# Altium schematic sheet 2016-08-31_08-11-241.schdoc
size 331 x 127 mm; SheetNumber: 1; SheetTotal: 1
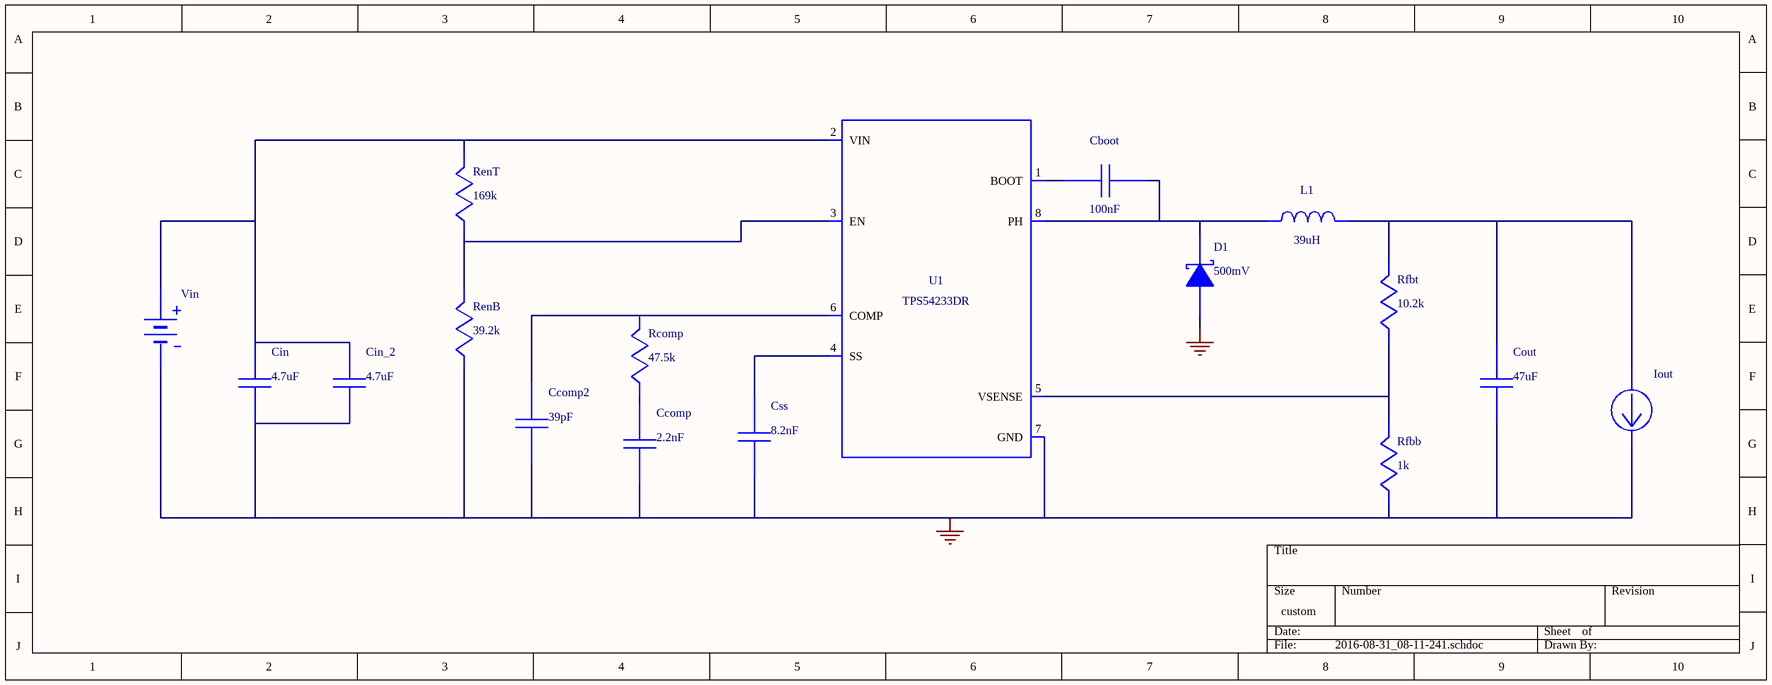
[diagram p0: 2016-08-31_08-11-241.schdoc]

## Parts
Cboot  value 100nF  (hidden comment: GRM155R61A104KA01D)
Ccomp  value 2.2nF  (hidden comment: CC0805KRX7R9BB222)
Ccomp2  value 39pF  (hidden comment: CC0805JRNPO9BN390)
Cin  value 4.7uF  (hidden comment: GRM32ER71H475KA88L)
Cin_2  value 4.7uF  (hidden comment: GRM32ER71H475KA88L)
Cout  value 47uF  (hidden comment: GRM32ER61C476ME15L)
Css  value 8.2nF  (hidden comment: GRM033R61A822KA01D)
D1  value 500mV  (hidden comment: B240A-13-F)
Iout  WB_CURRENT_LOAD  (value not drawn)
L1  value 39uH  (hidden comment: SRR1208-390YL)
Rcomp  value 47.5k  (hidden comment: CRCW040247K5FKED)
RenB  value 39.2k  (hidden comment: CRCW040239K2FKED)
RenT  value 169k  (hidden comment: CRCW0402169KFKED)
Rfbb  value 1k  (hidden comment: CRCW04021K00FKED)
Rfbt  value 10.2k  (hidden comment: CRCW040210K2FKED)
U1  TPS54231DR  (value not drawn)
Vin  WB_BATTERY  (value not drawn)

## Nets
0: Ccomp.2 Ccomp2.2 Cin.2 Cin_2.2 Cout.2 Css.2 D1.2(A) Iout.2(-) RenB.2 Rfbb.2 U1.7(GND) Vin.2(-)
NetCboot_1: Cboot.1 U1.1(BOOT)
NetCboot_2: Cboot.2 D1.1(K) L1.2 U1.8(PH)
NetCcomp2_1: Ccomp2.1 Rcomp.1 U1.6(COMP)
NetCcomp_1: Ccomp.1 Rcomp.2
NetCin_1: Cin.1 Cin_2.1 RenT.1 U1.2(VIN) Vin.1(+)
NetCout_1: Cout.1 Iout.1(+) L1.1 Rfbt.1
NetCss_1: Css.1 U1.4(SS)
NetRenB_1: RenB.1 RenT.2 U1.3(EN)
NetRfbb_1: Rfbb.1 Rfbt.2 U1.5(VSENSE)

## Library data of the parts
Cboot = GRM155R61A104KA01D: GRM155R61A104KA0; Manufacturer Name: MuRata
Ccomp = CC0805KRX7R9BB222: CC0805KRX7R9BB22; Manufacturer Name: Yageo America
Ccomp2 = CC0805JRNPO9BN390: CC0805JRNPO9BN39; Manufacturer Name: Yageo America
Cin Cin_2 = GRM32ER71H475KA88L: GRM32ER71H475KA8; Manufacturer Name: MuRata
Cout = GRM32ER61C476ME15L: GRM32ER61C476ME1; Manufacturer Name: MuRata
Css = GRM033R61A822KA01D: GRM033R61A822KA0; Manufacturer Name: MuRata
D1 = B240A-13-F: Manufacturer Name: Diodes Inc.
L1 = SRR1208-390YL: Manufacturer Name: Bourns
Rcomp = CRCW040247K5FKED: Manufacturer Name: Vishay-Dale
RenB = CRCW040239K2FKED: Manufacturer Name: Vishay-Dale
RenT = CRCW0402169KFKED: Manufacturer Name: Vishay-Dale
Rfbb = CRCW04021K00FKED: Manufacturer Name: Vishay-Dale
Rfbt = CRCW040210K2FKED: Manufacturer Name: Vishay-Dale
U1 = TPS54231DR: TPS54233DR; Manufacturer Name: Texas Instruments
